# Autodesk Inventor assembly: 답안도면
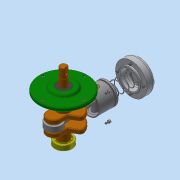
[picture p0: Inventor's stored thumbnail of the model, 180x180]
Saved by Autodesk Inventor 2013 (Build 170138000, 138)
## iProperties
Created: 2016-11
Part Number: 답안도면
Document SubType Name: Assembly
Designer: dgall
Author: dgall
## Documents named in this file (16)
- C:\Users\dgall\Desktop\361107V1012\답안도면.iam
- C:\Users\dgall\Desktop\361107V1012\본체.ipt
- C:\Users\dgall\Desktop\361107V1012\베어링 20 x 47 x 14.ipt
- C:\Users\dgall\Desktop\361107V1012\메인크랭크축.ipt
- C:\Users\dgall\Desktop\361107V1012\베어링 NA 4902.ipt
- C:\Users\dgall\Desktop\361107V1012\크랭크보조축.ipt
- C:\Users\dgall\Desktop\361107V1012\앞커버.ipt
- C:\Users\dgall\Desktop\361107V1012\오일 실 20 35 8.ipt
- C:\Users\dgall\Desktop\361107V1012\실린더.ipt
- C:\Users\dgall\Desktop\361107V1012\피스톤.ipt
- C:\Users\dgall\Desktop\361107V1012\커넥팅로드.ipt
- C:\Users\dgall\Desktop\361107V1012\피스톤핀.ipt
- C:\Users\dgall\Desktop\361107V1012\실린더헤드.ipt
- C:\Users\dgall\Desktop\361107V1012\가변스프링.ipt
- C:\Users\dgall\Desktop\361107V1012\볼트 M4 x 8.ipt
- C:\Users\dgall\Desktop\361107V1012\볼트 M5 x 20.ipt
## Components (15 placed, 5 different names)
1. 피스톤:1
2. 피스톤핀:1
3. 가변스프링:1
4. ISO 4762 M5 x 20:1
5. ISO 4762 M5 x 20:2
6. ISO 4762 M5 x 20:3
7. ISO 4762 M5 x 20:4
8. ISO 4762 M4 x 8:1
9. ISO 4762 M4 x 8:2
10. ISO 4762 M4 x 8:3
11. ISO 4762 M4 x 8:4
12. ISO 4762 M4 x 8:5
13. ISO 4762 M4 x 8:6
14. ISO 4762 M4 x 8:7
15. ISO 4762 M4 x 8:8
